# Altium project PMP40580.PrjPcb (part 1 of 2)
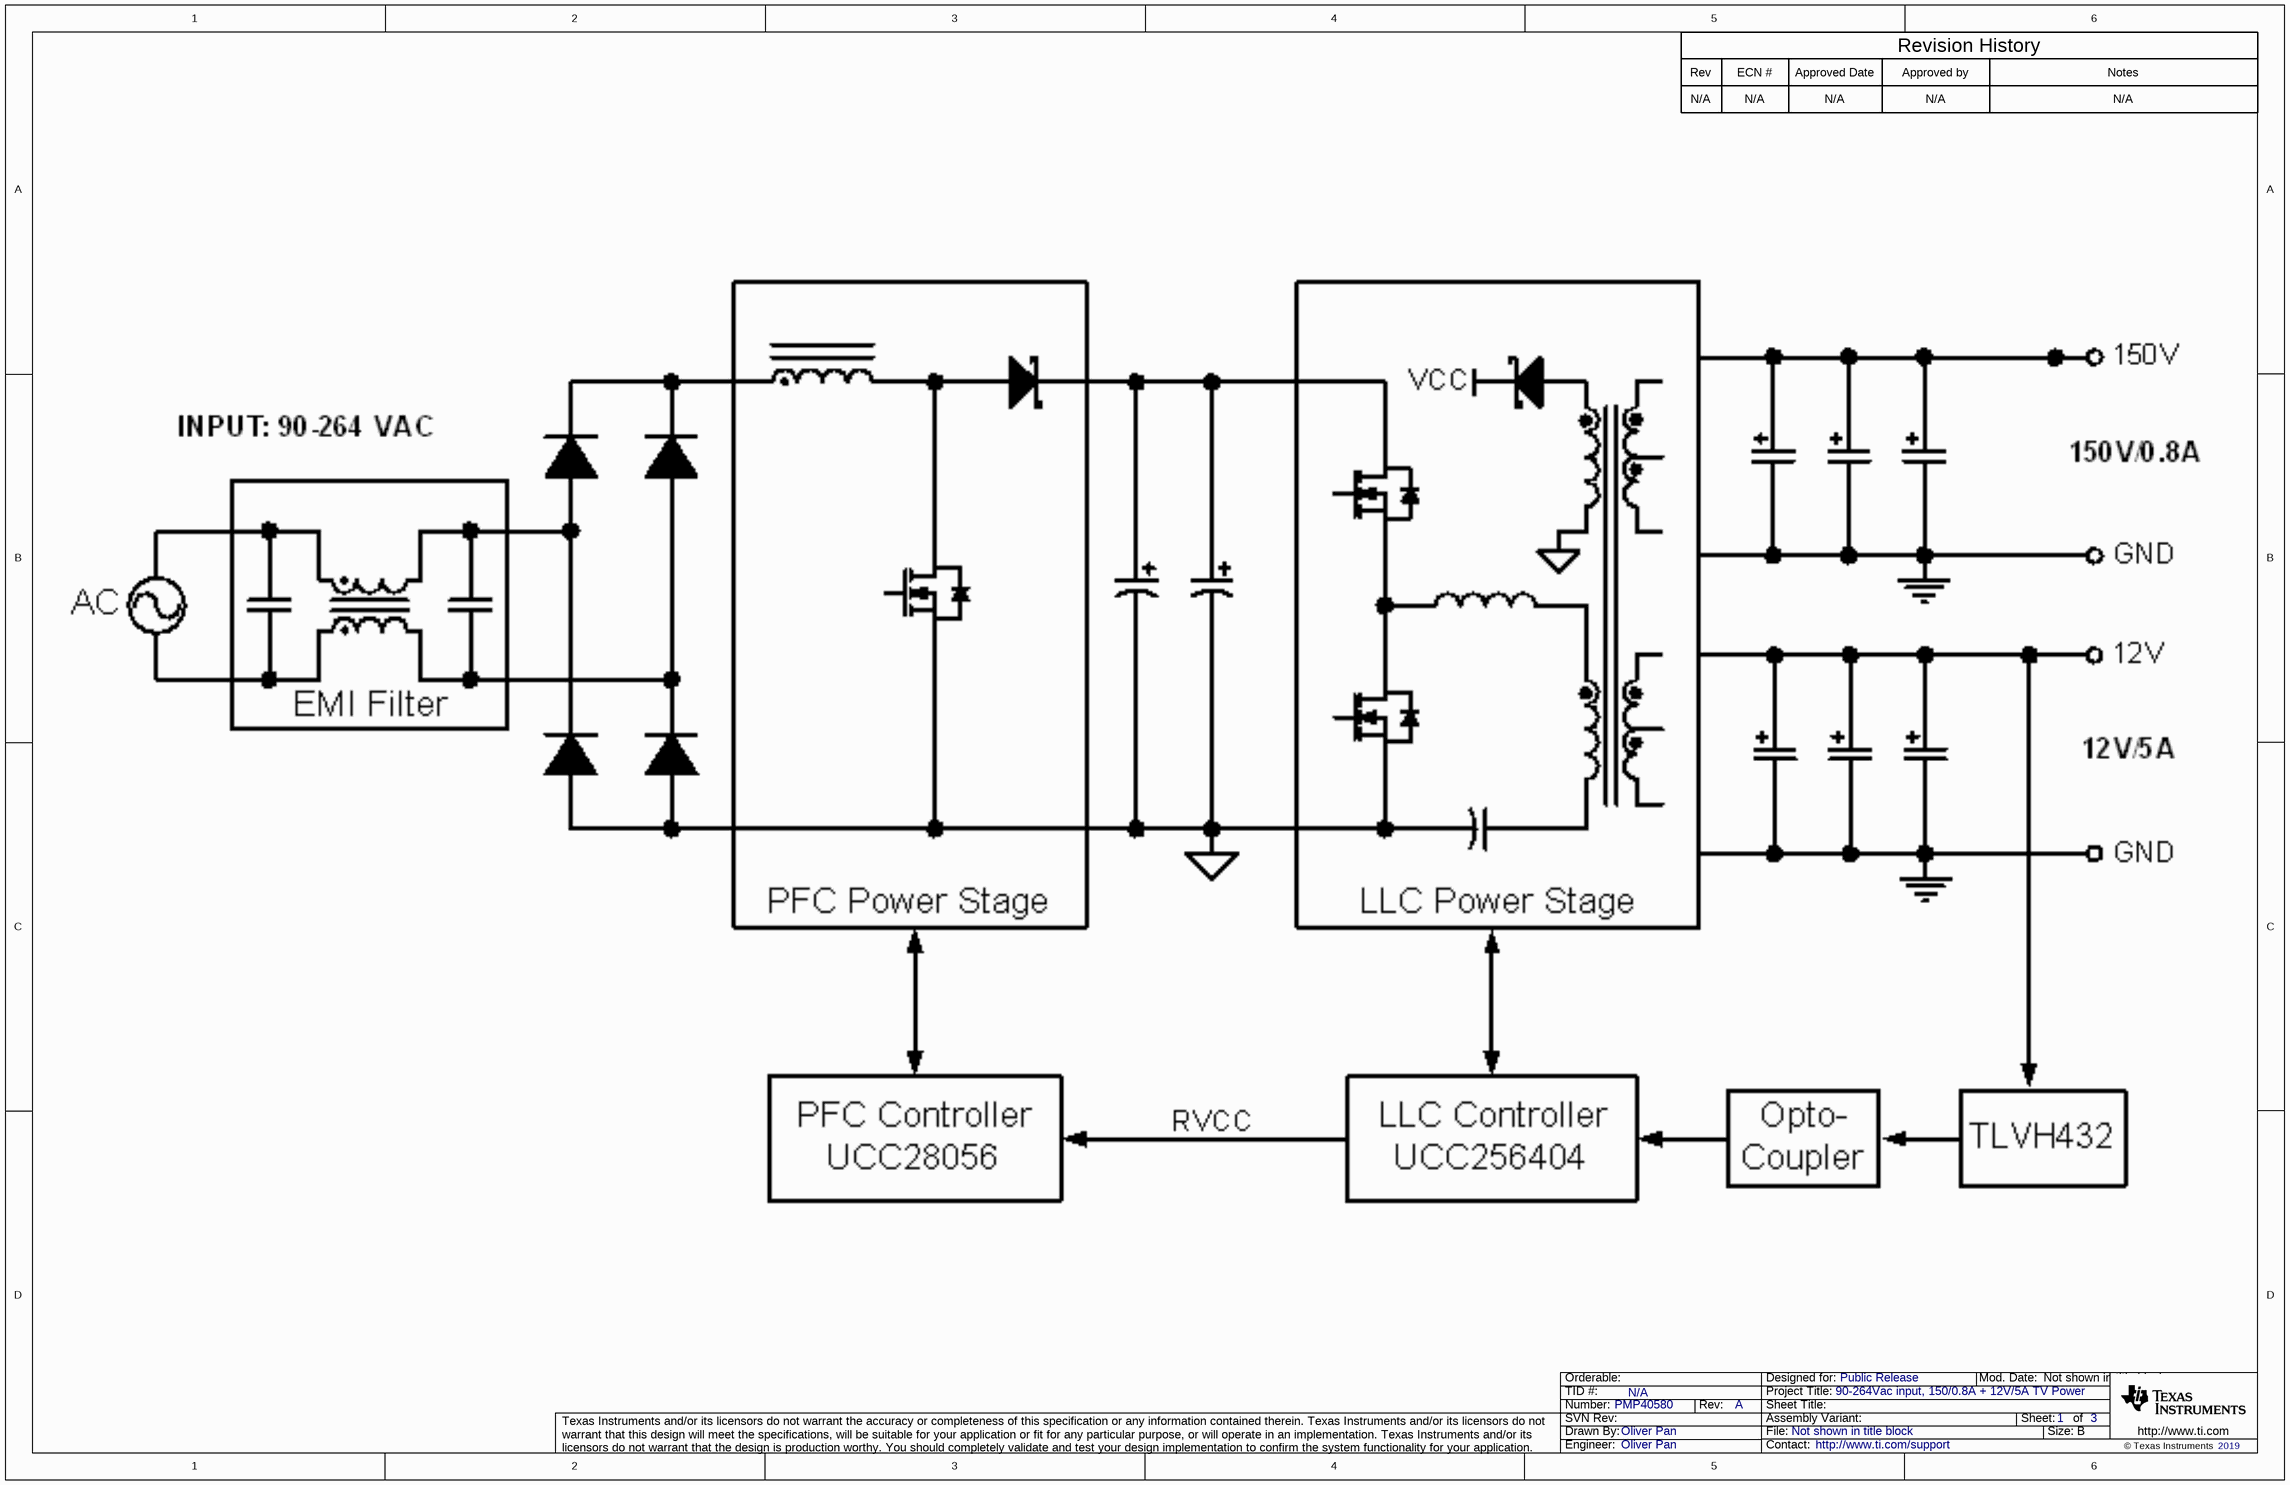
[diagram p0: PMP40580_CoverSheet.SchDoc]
CopyrightYear: 2019; PCB_Layout: Oliver Pan; PCB_Rev: A; PRJ_Customer: Public Release; PRJ_Engineer: Oliver Pan; PRJ_Number: PMP40580; PRJ_Title: 90-264Vac input, 150/0.8A + 12V/5A TV Power; SCH_Rev: A; TechSupport: http://www.ti.com/support; TID: N/A
3 sheets, 237 parts. Net scope: flat (ports and power ports of the same name join across sheets).
Board file: PMP40580_PCB.PcbDoc
Sheets:
  PMP40580_CoverSheet.SchDoc
  PMP40580_PFC.SchDoc
  PMP40580_LLC.SchDoc

## Sheet PMP40580_CoverSheet.SchDoc
size 431 x 279 mm; Date: Not shown in title block; ApprovedBy: Not shown in title block; CheckedBy: Not shown in title block; Author: Not shown in title block; CompanyName: Not shown in title block; DrawnBy: Oliver Pan; Engineer: Not shown in title block; Organization: Not shown in title block; Address1: Not shown in title block; Address2: Not shown in title block; Address3: Not shown in title block; Address4: Not shown in title block; DocumentNumber: 1; Revision: Use project parameter SCH_Rev; SheetNumber: 1; SheetTotal: 3; PageSetup: Record=PageOptions¦CenterHorizontal=True¦CenterVertical=True¦PrintScale=1.00¦XCorrection=1.00¦YCorrection=1.00¦PrintKind=0¦BorderSize=5000000¦LeftOffset=0¦BottomOffset=0¦Orientation=2¦PaperLength=1000¦PaperWidth=1000¦Scale=100¦PaperSource=15¦PrintQuality=600¦MediaType=1¦DitherType=10¦PaperKind=Letter¦PrintScaleMode=1

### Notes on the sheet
- Rev
- N/A
- ECN #
- Approved Date
- Approved by
- Revision History
- Notes

## Sheet PMP40580_PFC.SchDoc
size 431 x 279 mm; Date: Not shown in title block; ApprovedBy: Not shown in title block; CheckedBy: Not shown in title block; Author: Not shown in title block; CompanyName: Not shown in title block; DrawnBy: Oliver Pan; Engineer: Not shown in title block; Organization: Not shown in title block; Address1: Not shown in title block; Address2: Not shown in title block; Address3: Not shown in title block; Address4: Not shown in title block; DocumentNumber: 1; Revision: Use project parameter SCH_Rev; SheetNumber: 2; SheetTotal: 3; PageSetup: Record=PageOptions¦CenterHorizontal=True¦CenterVertical=True¦PrintScale=1.00¦XCorrection=1.00¦YCorrection=1.00¦PrintKind=0¦BorderSize=5000000¦LeftOffset=0¦BottomOffset=0¦Orientation=2¦PaperLength=1000¦PaperWidth=1000¦Scale=100¦PaperSource=15¦PrintQuality=600¦MediaType=1¦DitherType=10¦PaperKind=Letter¦PrintScaleMode=1
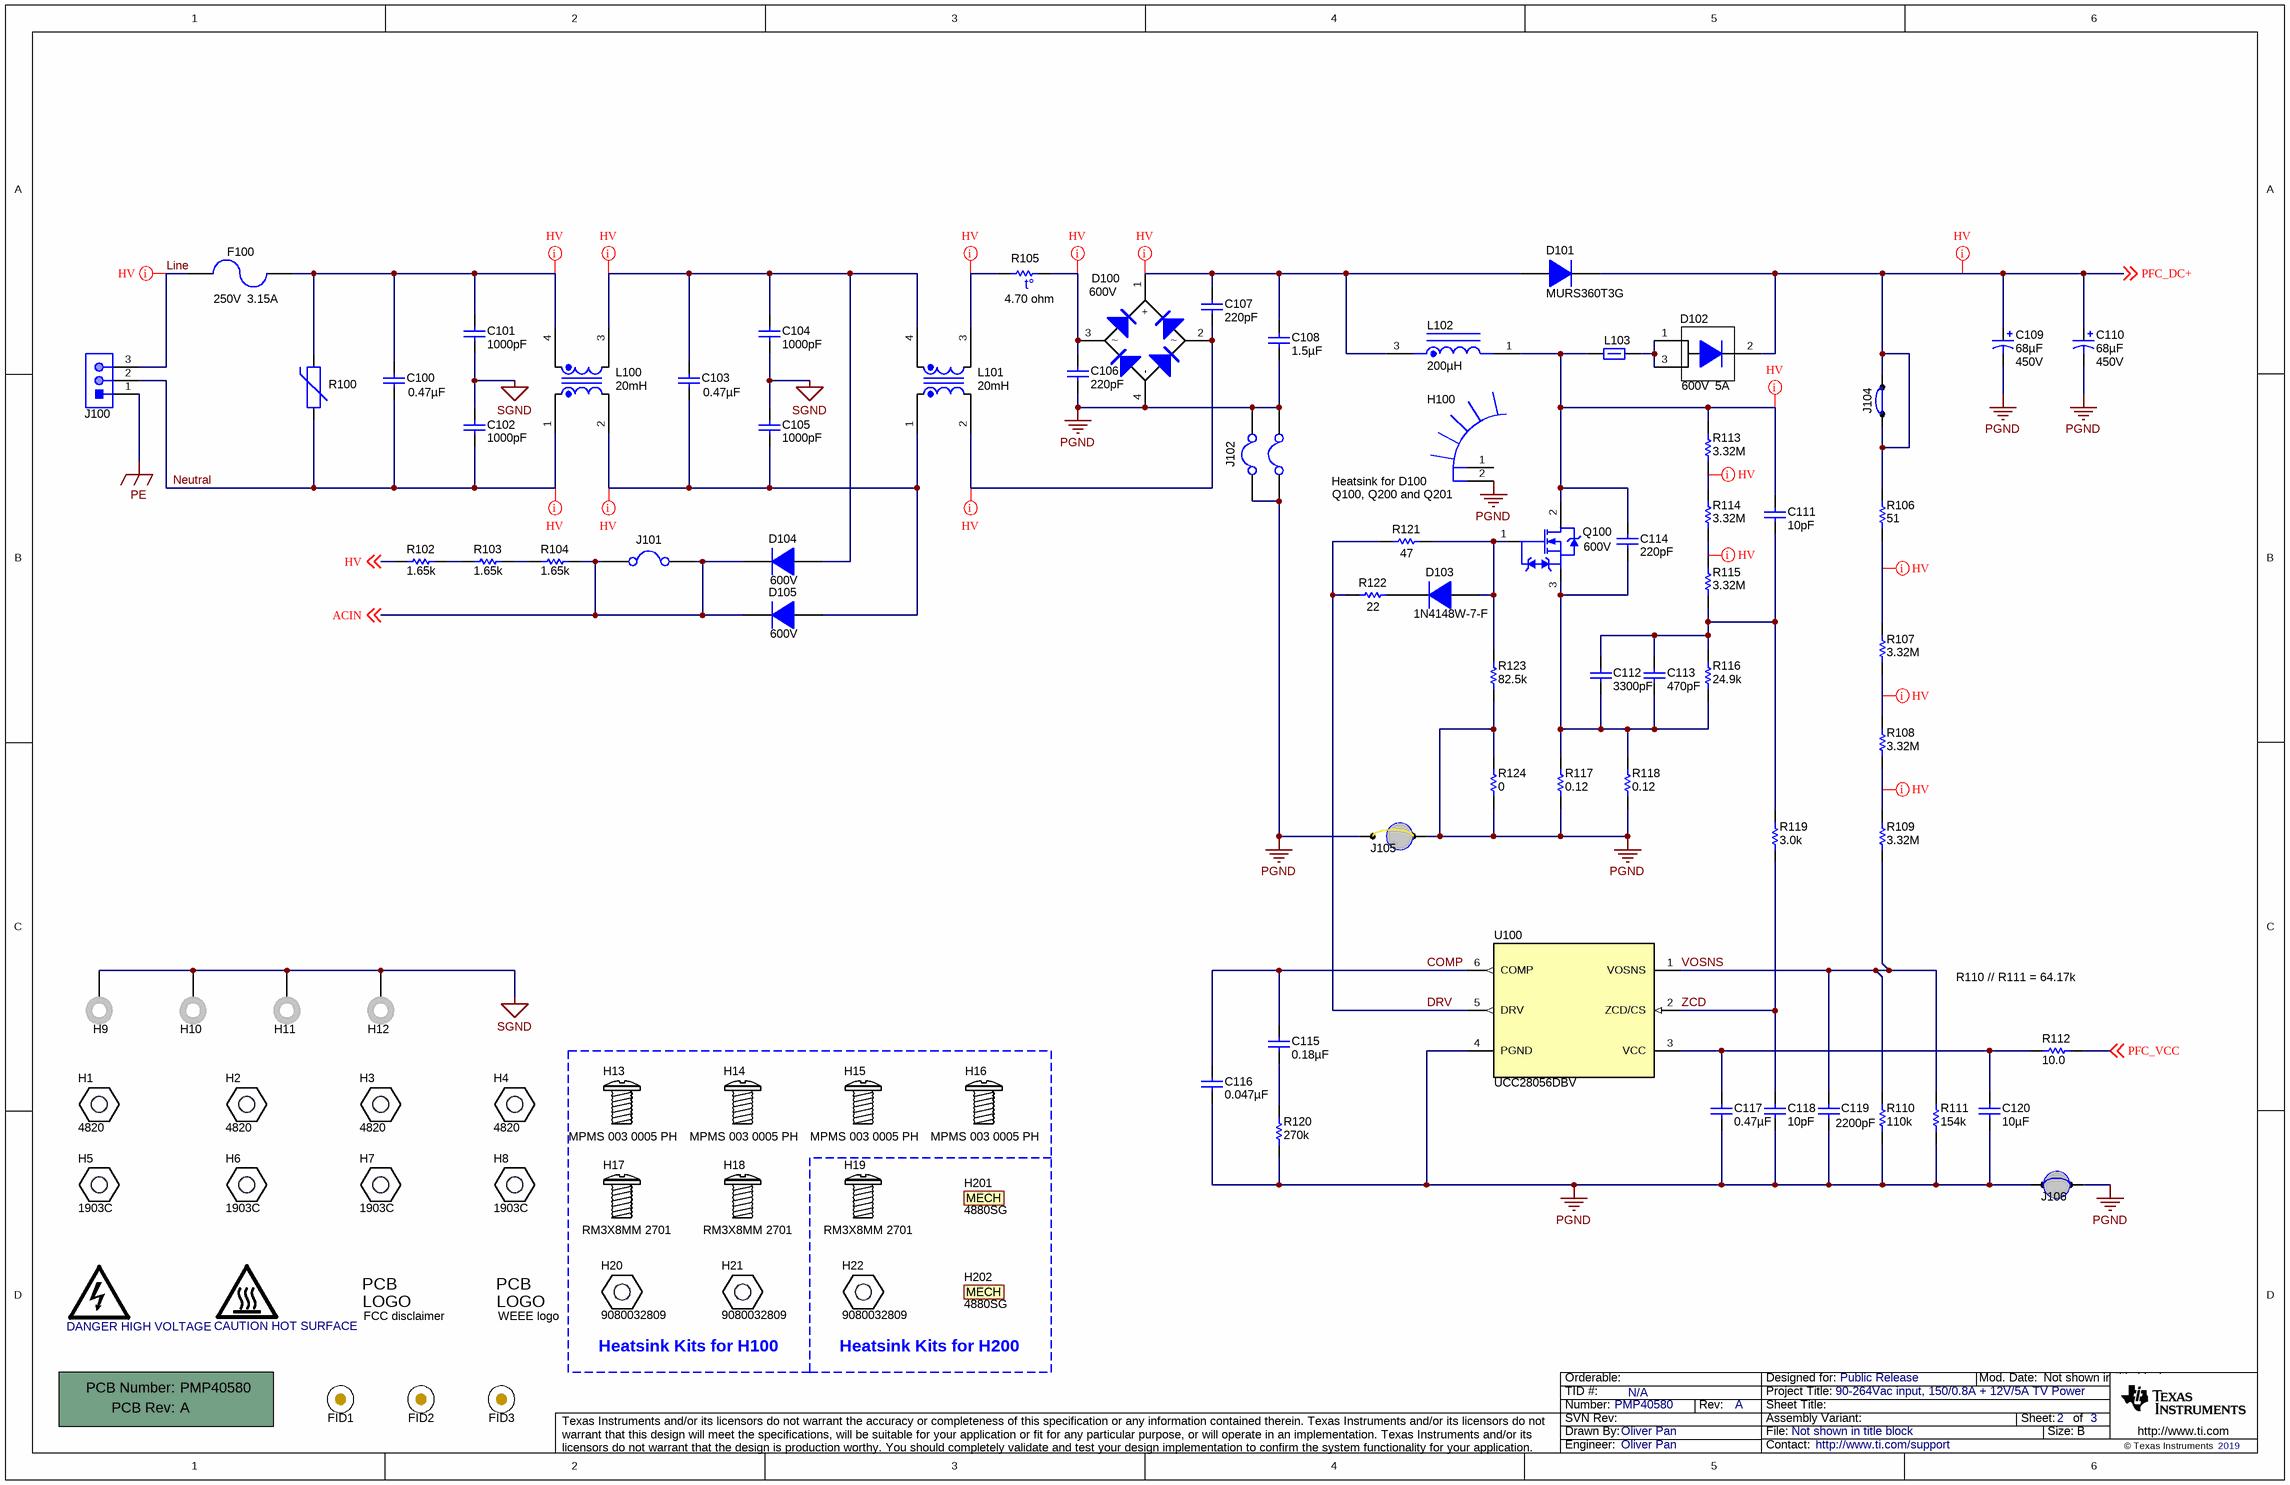
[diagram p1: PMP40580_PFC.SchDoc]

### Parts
!PCB  Printed Circuit Board  (value not drawn)  (mechanical)
C100  value 0.47µF  [CAPRR2250W80L2550T850H1750]  (hidden comment: ECQ-UAAF474M)
C101  ValueDisplayed: 1000pF  [CD45_700x600x1100]  (hidden comment: CD45-E2GA102M-NKA)
C102  ValueDisplayed: 1000pF  [CD45_700x600x1100]  (hidden comment: CD45-E2GA102M-NKA)
C103  value 0.47µF  [CAPRR2250W80L2550T850H1750]  (hidden comment: ECQ-UAAF474M)
C104  ValueDisplayed: 1000pF  [CD45_700x600x1100]  (hidden comment: CD45-E2GA102M-NKA)
C105  ValueDisplayed: 1000pF  [CD45_700x600x1100]  (hidden comment: CD45-E2GA102M-NKA)
C106  ValueDisplayed: 220pF  [CC45_850x500x1250]  (hidden comment: CC45SL3AD221JYNNA)
C107  ValueDisplayed: 220pF  [CC45_850x500x1250]  (hidden comment: CC45SL3AD221JYNNA)
C108  ValueDisplayed: 1.5µF  [ECQE_2570x820x1720]  (hidden comment: ECQ-E2W155KH)
C109  ValueDisplayed: 68µF  Value2: 450V  [BXW_1250x5000_Horizontal_DOWN]  (hidden comment: 450BXW68MEFC12.5X45)
C110  ValueDisplayed: 68µF  Value2: 450V  [BXW_1250x5000_Horizontal_DOWN]  (hidden comment: 450BXW68MEFC12.5X45)
C111  ValueDisplayed: 10pF  [1206]  (hidden comment: VJ1206A100JXGAT5Z)
C112  ValueDisplayed: 3300pF  [0805_HV]  (hidden comment: GRM2165C1H332JA01D)
C113  ValueDisplayed: 470pF  [0805_HV]  (hidden comment: 08055A471JAT2A)
C114  ValueDisplayed: 220pF  [CC45_850x500x1250]  (hidden comment: CC45SL3AD221JYNNA)
C115  ValueDisplayed: 0.18µF  [0805_HV]  (hidden comment: GRM21BR71E184KA01L)
C116  ValueDisplayed: 0.047µF  [0805_HV]  (hidden comment: GRM219R71E473KA01D)
C117  ValueDisplayed: 0.47µF  [0805_HV]  (hidden comment: GRM21BR71H474KA88L)
C118  ValueDisplayed: 10pF  [0805_HV]  (hidden comment: 08055A100JAT2A)
C119  ValueDisplayed: 2200pF  [0805_HV]  (hidden comment: GRM2165C1H222JA01D)
C120  ValueDisplayed: 10µF  [0805_HV]  (hidden comment: GRM21BZ71E106KE15L)
D100  value 600V  [FP-KBJ608G_BENT]  (hidden comment: TS15P05G)
D101  MURS360T3G  [SMC]
D102  value 600V  Value1: 5A  [DPAK]  (hidden comment: MURHD560T4G)
D103  1N4148W-7-F  [SOD-123]
D104  value 600V  [SMA]  (hidden comment: MURA160T3G)
D105  value 600V  [SMA]  (hidden comment: MURA160T3G)
F100  VAC_V: 250V  Irating_A: 3.15A  [FUSE_215]  (hidden comment: 02153.15MXEP)
FID1  Fiducial  [Fiducial10-20]  (value not drawn)
FID2  Fiducial  [Fiducial10-20]  (value not drawn)
FID3  Fiducial  [Fiducial10-20]  (value not drawn)
H1  4820  [KEYSTONE_4820]
H2  4820  [KEYSTONE_4820]
H3  4820  [KEYSTONE_4820]
H4  4820  [KEYSTONE_4820]
H5  1903C  [KEYSTONE_1903C]
H6  1903C  [KEYSTONE_1903C]
H7  1903C  [KEYSTONE_1903C]
H8  1903C  [KEYSTONE_1903C]
H9  (no value)  [GND CONNECT]
H10  (no value)  [GND CONNECT]
H11  (no value)  [GND CONNECT]
H12  (no value)  [GND CONNECT]
H13  MPMS 003 0005 PH  [BuildingFastener_MPMS_003_0005_PH]
H14  MPMS 003 0005 PH  [BuildingFastener_MPMS_003_0005_PH]
H15  MPMS 003 0005 PH  [BuildingFastener_MPMS_003_0005_PH]
H16  MPMS 003 0005 PH  [BuildingFastener_MPMS_003_0005_PH]
H17  RM3X8MM 2701  [APM_RM3X8MM 2701]
H18  RM3X8MM 2701  [APM_RM3X8MM 2701]
H19  RM3X8MM 2701  [APM_RM3X8MM 2701]
H20  9080032809  [9080032809]
H21  9080032809  [9080032809]
H22  9080032809  [9080032809]
H100  SK443100SA  [SK-443-AL-100]  (value not drawn)
H201  4880SG  (mechanical)
H202  4880SG  (mechanical)
J100  (no value)  [691312410003]
J101  923345-08-C  [FP-923345-08-C_JUMPER2-MFG]  (value not drawn)
J102  923345-08-C  [FP-923345-08-C_JUMPER2-MFG]  (value not drawn)
J103  923345-08-C  [FP-923345-08-C_JUMPER2-MFG]  (value not drawn)
J104  923345-06-C  [CONN_923345-06-C]  (value not drawn)
J105  923345-04-C  [3M_923345-04-C]  (value not drawn)
J106  923345-06-C  [CONN_923345-06-C]  (value not drawn)
L100  ValueDisplayed: 20mH  [JLB20213]  (hidden comment: JLB20213)
L101  ValueDisplayed: 20mH  [JLB20213]  (hidden comment: JLB20213)
L102  ValueDisplayed: 200µH  [JLC42178]  (hidden comment: JLC42184)
L103  28L0138-10R-10  [28L0138]  (value not drawn)
LOGO1  DANGER HIGH VOLTAGE  [IEC_HighVoltage_Medium]  (no BOM)
LOGO2  CAUTION HOT SURFACE  [IEC_HotSurface_Medium]  (no BOM)
Logo3  FCC disclaimer  [FCC_disclaimer]  (no BOM)
Logo4  WEEE logo  [WEEE_Minimum]  (no BOM)
Q100  value 600V  [TO-220FP_Horizontal_100mil_Standoff2300]  (hidden comment: STF24N60DM2)
R100  V300LA2P  [S237 - Horizontal_Down]  (value not drawn)
R102  ValueDisplayed: 1.65k  [1206L]  (hidden comment: CRCW12061K65FKEA)
R103  ValueDisplayed: 1.65k  [1206L]  (hidden comment: CRCW12061K65FKEA)
R104  ValueDisplayed: 1.65k  [1206L]  (hidden comment: CRCW12061K65FKEA)
R105  value 4.70 ohm  [S237 - Horizontal_Down]  (hidden comment: B57237S0479M000)
R106  ValueDisplayed: 51  [1206]  (hidden comment: CRCW120651R0JNEA)
R107  ValueDisplayed: 3.32M  [1206]  (hidden comment: CRCW12063M32FKEA)
R108  ValueDisplayed: 3.32M  [1206]  (hidden comment: CRCW12063M32FKEA)
R109  ValueDisplayed: 3.32M  [1206]  (hidden comment: CRCW12063M32FKEA)
R110  ValueDisplayed: 110k  [0805_HV]  (hidden comment: CRCW0805110KFKEA)
R111  ValueDisplayed: 154k  [0805_HV]  (hidden comment: CRCW0805154KFKEA)
R112  ValueDisplayed: 10.0  [1206]  (hidden comment: CRCW120610R0FKEA)
R113  ValueDisplayed: 3.32M  [1206]  (hidden comment: CRCW12063M32FKEA)
R114  ValueDisplayed: 3.32M  [1206]  (hidden comment: CRCW12063M32FKEA)
R115  ValueDisplayed: 3.32M  [1206]  (hidden comment: CRCW12063M32FKEA)
R116  ValueDisplayed: 24.9k  [0805_HV]  (hidden comment: ERJ-6ENF2492V)
R117  ValueDisplayed: 0.12  [1206]  (hidden comment: ERJ-8RSJR12V)
R118  ValueDisplayed: 0.12  [1206]  (hidden comment: ERJ-8RSJR12V)
R119  ValueDisplayed: 3.0k  [0805_HV]  (hidden comment: CRCW08053K00JNEA)
R120  ValueDisplayed: 270k  [0805_HV]  (hidden comment: CRCW0805270KJNEA)
R121  ValueDisplayed: 47  [0805_HV]  (hidden comment: CRCW080547R0JNEA)
R122  ValueDisplayed: 22  [0805_HV]  (hidden comment: CRCW080522R0JNEA)
R123  ValueDisplayed: 82.5k  [0805_HV]  (hidden comment: CRCW080582K5FKEA)
R124  ValueDisplayed: 0  [1206]  (hidden comment: CRCW12060000Z0EA)
U100  UCC28056DBV  [DBV0006A_N]

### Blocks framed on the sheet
Heatsink Kits for H100: H13-H18 H20 H21

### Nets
PE: J100.1
PGND: C106.1 C108.2 C109.2(-) C110.2(-) C116.2 C117.2 C118.2 C119.2 C120.2 D100.4(-) H100.2 J102.1 J102.2 J103.1 J103.2 J105.1 J105.2 J106.1 J106.2 R110.1 R111.1 R117.1 R118.1 R120.1 R123.1 R124.1 R124.2 U100.4(PGND)
SGND: C101.2 C102.2 C104.1 C105.2 H9.1 H10.1 H11.1 H12.1
ACIN: D104.1(K) D105.1(K) J101.1 J101.2 R104.2 ; off-sheet ACIN
COMP: C115.1 C116.1 U100.6(COMP)
DRV: R121.1 R122.1 U100.5(DRV)
HV: R102.1 ; off-sheet HV
Line: F100.2 J100.3
Neutral: C100.2 C102.1 J100.2 L100.1 R100.1
PFC_DC+: C109.1(+) C110.1(+) D101.1(K) D102.2(K) J104.1 J104.2 R106.2 ; off-sheet PFC_DC+
PFC_VCC: R112.2 ; off-sheet PFC_VCC
VOSNS: C119.1 R109.1 R110.2 R111.2 U100.1(VOSNS)
ZCD: C118.1 R119.1 U100.2(ZCD/CS)
NetC100_1: C100.1 C101.1 F100.1 L100.4 R100.2
NetC103_1: C103.1 C104.2 D104.2(A) L100.3 L101.4
NetC103_2: C103.2 C105.1 D105.2(A) L100.2 L101.1
NetC106_2: C106.2 D100.3 R105.2
NetC107_1: C107.1 D100.2 L101.2
NetC107_2: C107.2 C108.1 D100.1(+) D101.2(A) L102.3
NetC111_1: C111.1 C114.2 L102.1 L103.1 Q100.2(D) R113.2
NetC111_2: C111.2 C112.1 C113.1 R115.1 R116.2 R119.2
NetC112_2: C112.2 C113.2 C114.1 Q100.3(S) R116.1 R117.2 R118.2
NetC115_2: C115.2 R120.2
NetC117_1: C117.1 C120.1 R112.1 U100.3(VCC)
NetD102_1: D102.1(A) D102.3(A) L103.2
NetD103_1: D103.1(K) R122.2
NetD103_2: D103.2(A) Q100.1(G) R121.2 R123.2
NetL101_3: L101.3 R105.1
NetR102_2: R102.2 R103.1
NetR103_2: R103.2 R104.1
NetR106_1: R106.1 R107.2
NetR107_1: R107.1 R108.2
NetR108_1: R108.1 R109.2
NetR113_1: R113.1 R114.2
NetR114_1: R114.1 R115.2

Not connected (* = marked no-connect by the designer): H100 1

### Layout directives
rule Clearance Constraint [Clearance = 80mil]: Line, NetC100_1, NetC103_1, NetC103_2, NetC106_2, NetC107_1, NetC107_2, NetC111_1, NetL101_3, NetR106_1, NetR107_1, NetR108_1, NetR113_1, NetR114_1, Neutral, PFC_DC+

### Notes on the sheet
- Heatsink for D100
- (near H100) Q100, Q200 and Q201
- R110 // R111 = 64.17k
- Heatsink Kits for H200

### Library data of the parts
!PCB = CMP-0003618-2: Manufacturer: Any; PartNumber: PMP40580
C100 C103 = ECQ-U2A474ML: CAP, Film, 0.47 µF, 275 V,+/- 20%, TH; Manufacturer: Panasonic; Dielectric Material: PP; Voltage Rating (AC): 275V; Lead/Base Style: Straight; Lead Diameter: 0.8mm
C101 C102 C104 C105 = CD45-E2GA102M-NKA: CAP, CERM, 1000 pF, X1 440 VAC/Y1 400 VAC, +/- 20%, E, D7xT6mm; Manufacturer: TDK; Polarized: N; CompType: Capacitor; Value: 1000pF; U/M: EA; Cap_F: 0.000000001; Tolerance_%: 20; TaMin_C: -25; TaMax_C: 125; Cap_Case: 7x6x11mm; SizeArea_mm2: 63.9; SizeAreaWB_mm2: 101.2; SizeX_mm: 10.65; SizeY_mm: 6; SizeZ_mm: 11; AEC Category: Q200; AC_Safety: X1Y1; VAC_X: 440; VAC_Y: 400
C106 C107 C114 = CC45SL3AD221JYNNA: CAP, CERM, 220 pF, 1000 V,+/- 5%, SL, D8.5xT5mm; Manufacturer: TDK; Polarized: N; CompType: Capacitor; Value: 220pF; U/M: EA; Cap_F: 0.00000000022; Tolerance_%: 5; VDC_V: 1000; Value2: 1000V; TaMin_C: -25; TaMax_C: 125; Cap_Case: 8.5x5x12.5mm; SizeArea_mm2: 42.5; SizeAreaWB_mm2: 73.5; SizeX_mm: 8.5; SizeZ_mm: 12.5; AEC Category: Q200
C108 = ECQ-E2W155KH: CAP, Film, 1.5 µF, 450 V,+/- 10%, TH; Manufacturer: Panasonic; Polarized: N; CompType: Capacitor; Value: 1.5uF; U/M: EA; Cap_F: 0.0000015; Tolerance_%: 10; VDC_V: 450; Value2: 450V; TaMin_C: -40; TaMax_C: 105; AEC Category: Q200; Green_Lifecycle: Not Set; Green_REACh: Incomplete
C109 C110 = 450BXW68MEFC12.5X45: CAP, AL, 68 µF, 450 V, +/- 20%, TH; Manufacturer: Rubycon; Polarized: Y; CompType: Capacitor; Value: 68uF; U/M: EA; Cap_F: 0.000068; Tolerance_%: 20; Value1: Unknown; VDC_V: 450; IRMS_A: 0.61; TaMin_C: -40; TaMax_C: 105; Cap_Case: 12.5X45mm; SizeAreaWB_mm2: 210.25; SizeArea_mm2: 156.25; SizeX_mm: 12.5; SizeZ_mm: 47; AEC Category: Q200; AEC Qualified: N
C111 = VJ1206A100JXGAT5Z: CAP, CERM, 10 pF, 1000 V,+/- 5%, C0G/NP0, 1206; Manufacturer: Vishay-Vitramon; Polarized: N; CompType: Capacitor; Value: 10pF; U/M: EA; Cap_F: 0.00000000001; Tolerance_%: 5; VDC_V: 1000; Value2: 1000V; TaMin_C: -55; TaMax_C: 125; SizeArea_mm2: 5.12; SizeAreaWB_mm2: 10.92; SizeX_mm: 3.2; SizeY_mm: 1.6; SizeZ_mm: 1.35; AEC Category: Q200
C112 = GRM2165C1H332JA01D: CAP, CERM, 3300 pF, 50 V,+/- 5%, C0G/NP0, 0805; Manufacturer: MuRata; Polarized: N; CompType: Capacitor; Value: 3300pF; U/M: EA; Cap_F: 0.0000000033; Tolerance_%: 5; VDC_V: 50; Value2: 50V; TaMin_C: -55; TaMax_C: 125; Cap_Case: 0805; SizeArea_mm2: 2.5; SizeAreaWB_mm2: 6.75; SizeX_mm: 2; SizeY_mm: 1.25; SizeZ_mm: 1.45; AEC Category: Q200
C113 = 08055A471JAT2A: CAP, CERM, 470 pF, 50 V,+/- 5%, C0G/NP0, 0805; Manufacturer: AVX; Polarized: N; CompType: Capacitor; Value: 470pF; U/M: EA; Cap_F: 0.00000000047; Tolerance_%: 5; ESR_ohm: 0.159; Value1: 0.159 ohm; VDC_V: 50; Value2: 50V; TaMin_C: -55; TaMax_C: 125; Cap_Case: 0805; SizeArea_mm2: 2.5; SizeAreaWB_mm2: 6.75; SizeX_mm: 2; SizeY_mm: 1.25; SizeZ_mm: 1.45; AEC Category: Q200; Green_Lifecycle: Not Set; Green_REACh: Incomplete
C115 = GRM21BR71E184KA01L: CAP, CERM, 0.18 µF, 25 V,+/- 10%, X7R, 0805; Manufacturer: MuRata; Polarized: N; CompType: Capacitor; Value: 0.18uF; U/M: EA; Cap_F: 0.00000018; Tolerance_%: 10; VDC_V: 25; Value2: 25V; TaMin_C: -55; TaMax_C: 125; Cap_Case: 0805; SizeArea_mm2: 2.5; SizeAreaWB_mm2: 6.75; SizeX_mm: 2; SizeY_mm: 1.25; SizeZ_mm: 1.45; AEC Category: Q200
C116 = GRM219R71E473KA01D: CAP, CERM, 0.047 µF, 25 V,+/- 10%, X7R, 0805; Manufacturer: MuRata; Polarized: N; CompType: Capacitor; Value: 0.047uF; U/M: EA; Cap_F: 0.000000047; Tolerance_%: 10; VDC_V: 25; Value2: 25V; TaMin_C: -55; TaMax_C: 125; Cap_Case: 0805; SizeArea_mm2: 2.5; SizeAreaWB_mm2: 6.75; SizeX_mm: 2; SizeY_mm: 1.25; SizeZ_mm: 1.45; AEC Category: Q200
C117 = GRM21BR71H474KA88L: CAP, CERM, 0.47 µF, 50 V,+/- 10%, X7R, 0805; Manufacturer: MuRata; Polarized: N; CompType: Capacitor; Value: 0.47uF; U/M: EA; Cap_F: 0.00000047; Tolerance_%: 10; VDC_V: 50; Value2: 50V; TaMin_C: -55; TaMax_C: 125; Cap_Case: 0805; SizeArea_mm2: 2.5; SizeAreaWB_mm2: 6.75; SizeX_mm: 2; SizeY_mm: 1.25; SizeZ_mm: 1.45; AEC Category: Q200; Green_Lifecycle: Active; Green_REACh: Passed
C118 = 08055A100JAT2A: CAP, CERM, 10 pF, 50 V, +/- 5%, C0G/NP0, 0805; Manufacturer: AVX; Polarized: N; CompType: Capacitor; Value: 10pF; U/M: EA; Cap_F: 0.00000000001; Tolerance_%: 5; ESR_ohm: 1.561; Value1: 1.561 ohm; VDC_V: 50; Value2: 50V; TaMin_C: -55; TaMax_C: 125; Cap_Case: 0805; SizeArea_mm2: 2.5; SizeAreaWB_mm2: 6.75; SizeX_mm: 2; SizeY_mm: 1.25; SizeZ_mm: 1.45; AEC Category: Q200
C119 = GRM2165C1H222JA01D: CAP, CERM, 2200 pF, 50 V,+/- 5%, C0G/NP0, 0805; Manufacturer: MuRata; Polarized: N; CompType: Capacitor; Value: 2200pF; U/M: EA; Cap_F: 0.0000000022; Tolerance_%: 5; VDC_V: 50; Value2: 50V; TaMin_C: -55; TaMax_C: 125; Cap_Case: 0805; SizeArea_mm2: 2.5; SizeAreaWB_mm2: 6.75; SizeX_mm: 2; SizeY_mm: 1.25; SizeZ_mm: 1.45; AEC Category: Q200; Green_Lifecycle: Active; Green_REACh: Passed
C120 = GRM21BZ71E106KE15L: CAP, CERM, 10 µF, 25 V, +/- 10%, X7R, 0805; Manufacturer: MuRata; Polarized: N; CompType: Capacitor; Value: 10uF; U/M: EA; Cap_F: 0.00001; Tolerance_%: 10; Value1: Unknown; VDC_V: 25; Value2: 25V; TaMin_C: -55; TaMax_C: 125; Cap_Case: 0805; SizeArea_mm2: 2.5; SizeAreaWB_mm2: 6.75; SizeX_mm: 2; SizeY_mm: 1.25; SizeZ_mm: 1.45; AEC Category: Q200
D100 = GBU4J-BP: Diode, P-N-Bridge, 600 V, 15 A, TH; Manufacturer: Taiwan Semiconductor Corporation; U/M: EA; Vf_V: 1; Value1: 15A; Value2: 1V; Io_A: 4; Vr_V: 600; TJmax_C: 150; RJC_CperW: 2.2; SizeAreaWB_mm2: 130.5915; SizeArea_mm2: 75.6315; SizeX_mm: 22.05; SizeY_mm: 3.43; SizeZ_mm: 21.55; AEC Category: Q101
D101 = MURS360T3G: Diode, Ultrafast, 600 V, 3 A, SMC; Manufacturer: ON Semiconductor; U/M: EA; Vf_V: 1.25; Value: 600V; Value1: 3A; Value2: 1.25V; Io_A: 3; Vr_V: 600; TJmax_C: 175; RJC_CperW: 11; SizeAreaWB_mm2: 83.2686; SizeArea_mm2: 50.5686; SizeX_mm: 8.13; SizeY_mm: 6.22; SizeZ_mm: 2.6; AEC Category: Q101; Green_Lifecycle: Active; Green_REACh: Passed
D102 = CMP-0077041-3: Diode, Ultrafast, 600 V, 5 A, DPAK; Manufacturer: ON Semiconductor; SizeX_mm: 9.91; TJmax_C: 175°C; Green_Lifecycle: Not Set; Green_REACh: Incomplete; SizeZ_mm: 2.29; SizeY_mm: 6.54; SizeArea_mm2: 64.8114; SizeAreaWB_mm2: 101.7114; Value2: 2.7V; RJC_CperW: 2.5; AEC Category: Q101
D103 = 1N4148W-7-F: Diode, Ultrafast, 100 V, 0.15 A, SOD-123; Manufacturer: Diodes Inc.; U/M: EA; Vf_V: 1.25; Value: 100V; Value1: 0.15A; Value2: 1.25V; Io_A: 0.15; Vr_V: 100; TJmax_C: 150; SizeAreaWB_mm2: 13.095; SizeArea_mm2: 6.545; SizeX_mm: 3.85; SizeY_mm: 1.7; SizeZ_mm: 1.35; AEC Category: Q101
D104 D105 = MURA160T3G: Diode, Ultrafast, 600 V, 1 A, AEC-Q101, SMA; Manufacturer: ON Semiconductor; U/M: EA; Vf_V: 1.05; Value1: 1A; Value2: 1.05V; Io_A: 1; Vr_V: 600; TJmax_C: 175; SizeAreaWB_mm2: 37.3428; SizeArea_mm2: 16.3228; SizeX_mm: 5.59; SizeY_mm: 2.92; SizeZ_mm: 2.87; AEC Category: Q101; AEC Qualified: Y
F100 = 02153.15MXEP: Fuse, 3.15 A, 250 VAC, TH; Manufacturer: Littelfuse; Interrupt_AC: 1500; Rtyp_Ohm: 0.0283; MeltingTyp: 43.255
FID1-FID3 = CMP-0077181-1: Fiducial mark.  There is nothing to buy or mount.
H1-H4 = 4820: Standoff, Hex, 1"L #6-32 Nylon, M-F; Manufacturer: Keystone; SymbolCreator: a0412235; Green_Lifecycle: Active; Green_REACh: Passed
H5-H8 = CMP-0003679-1: Manufacturer: Keystone; CompType: Standoff
H9-H12 = 108-0740-001: GND connector
H13-H16 = MPMS 003 0005 PH: MACHINE SCREW PAN PHILLIPS M3 5mm; Manufacturer: B&F Fastener Supply; SymbolCreator: a0412235; Green_Lifecycle: Not Set; Green_REACh: Incomplete
H17-H19 = RM3X8MM 2701: MACHINE SCREW PAN PHILLIPS M3; Manufacturer: APM HEXSEAL; SymbolCreator: a0412235; Green_Lifecycle: Not Set; Green_REACh: Incomplete
H20-H22 = 9080032809: Hex Nuts: M3 X .5MM pitch DIN 934 A2 - 304 Stainless; Manufacturer: InStock Fasteners; SymbolCreator: a0412235; CompType: Nut; Green_Lifecycle: Not Set; Green_REACh: Incomplete
H100 = HeatSink_2840x500x600_PQFP64-PBH: Extruded Heatsink, 100mm, CUSTOM; Manufacturer: Texas Instruments; SymbolCreator: a0799628
H201 H202 = MechPart: TO-220 Mounting Kit; Manufacturer: Aavid Thermalloy; SymbolCreator: codlsc; CompType: Mechanical; U/M: EA
J100 = 691312410003: Serie 3124 - 7.62mm Open Horizontal PCB Header WR-TBL, 3 pin; Pin Number: 3; Gender: Male
J101-J103 = CMP-0086939-1: Manufacturer: 3M; ContactFinish: Tin
J104 J106 = 923345-06-C: Jumper Wire, 600mil spacing, Blue, pkg of 150, TH; Manufacturer: 3M; SymbolCreator: a0412235; Green_Lifecycle: Active; Green_REACh: Passed
J105 = 923345-04-C: Jumper Wire, 400 mil Spacing, Yellow, Pkg of 200; Manufacturer: 3M; SymbolCreator: Altium; Green_Lifecycle: Active; Green_REACh: Passed
L100 L101 = PMP40348 CM: Coupled inductor, 20 mH, 3 A, 0.16 ohm, TH; Manufacturer: Jewel; Value: 20mH; Ind_H: 20.0E-3; DCR_ohm: 0.16
L102 = BK-35: Inductor, 200 µH, 0.235 ohm, TH; Manufacturer: Jewel; SymbolCreator: Altium; Ind_H: 200.0E-6; DCR_ohm: 0.235; Value2: A; SizeAreaWB_mm2: 792.9856; SizeArea_mm2: 684.3456; SizeX_mm: 26.16; SizeZ_mm: 19.05; AEC Category: Q200; AEC Qualified: N
L103 = 28L0138-10R-10: Ferrite Bead, 75 ohm @ 100 MHz, 5 A, D3.51xL4.45mm; Manufacturer: Laird-Signal Integrity Products; ValueDisplayed: 75 ohm; Value: 75 ohm; Imax_A: 5; DCR_ohm: 0.01; Value1: 0.01 ohm; Value2: 5A; SizeAreaWB_mm2: 60.2243; SizeArea_mm2: 31.3443; SizeX_mm: 8.93; SizeY_mm: 3.51; SizeZ_mm: 3.76; ZTyp@100MHz_Ohm: 75; Green_Lifecycle: Not Set; Green_REACh: Incomplete
LOGO1 = CMP-0074835-1: IEC 61010-1 High Voltage Warning; Library Reference: IEC_HighVoltage; SymbolCreator: a0412235
LOGO2 = CMP-0074837-1: IEC 61010-1 Hot Surface Warning; Library Reference: IEC_HotSurface; SymbolCreator: a0412235
Logo3 = CMP-0074847-1: FCC_disclaimer; Library Reference: Logo
Logo4 = CMP-0074769-1
Q100 = STF24N60DM2: MOSFET, N-CH, 600 V, 18 A, TO-220FP; Manufacturer: STMicroelectronics; Alternate Manufacturer: None; U/M: EA; ChType: N; VdsMax_V: 600; Value1: ? ohm; Value2: 29 nC; QgTyp_nC: 29; Vgs_V: 25; IdsMax_A: 18; SizeAreaWB_mm2: 79.3; SizeArea_mm2: 45.9; SizeX_mm: 10.2; SizeY_mm: 4.5; SizeZ_mm: 20; AEC Category: Q101; Green_Lifecycle: Active; Green_REACh: Passed; SymbolCreator: x0208325
R100 = V300LA2P: VARISTOR 490V 1.2KA DISC 7MM; Manufacturer: Littelfuse; SymbolCreator: a0412235
R102-R104 = CMP-0016708-3: RES, 1.65 k, 1%, 0.25 W, AEC-Q200 Grade 0, 1206; Manufacturer: Vishay-Dale; Power_W: 250mW; TempCo: 100 ppm/C; Value_Code: 1k65; Value: 1.65k; EIA_Code: E96; SizeX_mm: 3.2; SizeY_mm: 1.6; SizeZ_mm: 1.35; Value2: 0.25W; SizeArea_mm2: 5.12; CompType: Resistor; AEC Qualified: Y; VDC_V: 200V; AEC Category: Q200; AEC Grade: 0
R105 = B57237S0479M000: Thermistor NTC, 4.70 ohm, 20%, 15x7mm; Manufacturer: TDK; Tolerance_%: 20; Power_W: 3.1; TaMin_C: -55; TaMax_C: 170; U/M: EA
R106 = CRCW120651R0JNEA: RES, 51, 5%, 0.25 W, 1206; Manufacturer: Vishay-Dale; CompType: Resistor; Value: 51; Value_Code: 51R0; Tolerance_%: 5; Power_W: 0.25; Value2: 0.25W; VDC_V: 200; TempCo: 200 ppm/C; SizeArea_mm2: 5.12; SizeX_mm: 3.2; SizeY_mm: 1.6; SizeZ_mm: 1.35; EIA_Code: E24; U/M: EA; AEC Category: Q200
R107-R109 R113-R115 = CRCW12063M32FKEA: RES, 3.32 M, 1%, 0.25 W, 1206; Manufacturer: Vishay-Dale; CompType: Resistor; Value: 3.32Meg; Res_ohm: 3320000; Value_Code: 3M32; Tolerance_%: 1; Power_W: 0.25; Value2: 0.25W; VDC_V: 200; TempCo: 100 ppm/C; SizeArea_mm2: 5.12; SizeX_mm: 3.2; SizeY_mm: 1.6; SizeZ_mm: 1.35; EIA_Code: E96; U/M: EA; AEC Category: Q200
R110 = CRCW0805110KFKEA: RES, 110 k, 1%, 0.125 W, 0805; Manufacturer: Vishay-Dale; CompType: Resistor; Value: 110k; Res_ohm: 110000; Tolerance_%: 1; Power_W: 0.125; Value2: 0.125W; VDC_V: 150; TempCo: 100 ppm/C; SizeArea_mm2: 2.5; SizeX_mm: 2; SizeY_mm: 1.25; SizeZ_mm: 1.45; EIA_Code: E96; U/M: EA; AEC Category: Q200; Green_Lifecycle: Active; Green_REACh: Passed
R111 = CRCW0805154KFKEA: RES, 154 k, 1%, 0.125 W, 0805; Manufacturer: Vishay-Dale; CompType: Resistor; Value: 154k; Res_ohm: 154000; Tolerance_%: 1; Power_W: 0.125; Value2: 0.125W; VDC_V: 150; TempCo: 100 ppm/C; SizeArea_mm2: 2.5; SizeX_mm: 2; SizeY_mm: 1.25; SizeZ_mm: 1.45; EIA_Code: E96; U/M: EA; AEC Category: Q200; Green_Lifecycle: Active; Green_REACh: Passed
R112 = CRCW120610R0FKEA: RES, 10.0, 1%, 0.25 W, 1206; Manufacturer: Vishay-Dale; CompType: Resistor; Value: 10.0; Res_ohm: 10; Value_Code: 10R0; Tolerance_%: 1; Power_W: 0.25; Value2: 0.25W; VDC_V: 200; TempCo: 100 ppm/C; SizeArea_mm2: 5.12; SizeX_mm: 3.2; SizeY_mm: 1.6; SizeZ_mm: 1.35; EIA_Code: E96; U/M: EA; AEC Category: Q200
R116 = ERJ-6ENF2492V: RES, 24.9 k, 1%, 0.125 W, 0805; Manufacturer: Panasonic; CompType: Resistor; Value: 24.9k; Res_ohm: 24900; Value_Code: 24k9; Tolerance_%: 1; Power_W: 0.125; Value2: 0.125W; TempCo: 100 ppm/C; SizeArea_mm2: 2.5; SizeX_mm: 2; SizeY_mm: 1.25; SizeZ_mm: 1.45; EIA_Code: E96; U/M: EA; AEC Category: Q200
R117 R118 = ERJ-8RSJR12V: RES, 0.12, 5%, 0.25 W, 1206; Manufacturer: Panasonic; CompType: Resistor; Value: 0.12; Value_Code: R120; Tolerance_%: 5; Power_W: 0.25; Value2: 0.25W; TempCo: 250 ppm/C; SizeArea_mm2: 5.12; SizeX_mm: 3.2; SizeY_mm: 1.6; SizeZ_mm: 1.35; EIA_Code: E24; U/M: EA; AEC Category: Q200
R119 = CRCW08053K00JNEA: RES, 3.0 k, 5%, 0.125 W, 0805; Manufacturer: Vishay-Dale; CompType: Resistor; Value: 3.0k; Res_ohm: 3000; Value_Code: 3k00; Tolerance_%: 5; Power_W: 0.125; Value2: 0.125W; VDC_V: 150; TempCo: 200 ppm/C; SizeArea_mm2: 2.5; SizeX_mm: 2; SizeY_mm: 1.25; SizeZ_mm: 1.45; EIA_Code: E24; U/M: EA; AEC Category: Q200
R120 = CRCW0805270KJNEA: RES, 270 k, 5%, 0.125 W, 0805; Manufacturer: Vishay-Dale; CompType: Resistor; Value: 270k; Res_ohm: 270000; Tolerance_%: 5; Power_W: 0.125; Value2: 0.125W; VDC_V: 150; TempCo: 200 ppm/C; SizeArea_mm2: 2.5; SizeX_mm: 2; SizeY_mm: 1.25; SizeZ_mm: 1.45; EIA_Code: E24; U/M: EA; AEC Category: Q200
R121 = CRCW080547R0JNEA: RES, 47, 5%, 0.125 W, 0805; Manufacturer: Vishay-Dale; CompType: Resistor; Value: 47; Value_Code: 47R0; Tolerance_%: 5; Power_W: 0.125; Value2: 0.125W; VDC_V: 150; TempCo: 200 ppm/C; SizeArea_mm2: 2.5; SizeX_mm: 2; SizeY_mm: 1.25; SizeZ_mm: 1.45; EIA_Code: E24; U/M: EA; AEC Category: Q200
R122 = CRCW080522R0JNEA: RES, 22, 5%, 0.125 W, 0805; Manufacturer: Vishay-Dale; CompType: Resistor; Value: 22; Value_Code: 22R0; Tolerance_%: 5; Power_W: 0.125; Value2: 0.125W; VDC_V: 150; TempCo: 200 ppm/C; SizeArea_mm2: 2.5; SizeX_mm: 2; SizeY_mm: 1.25; SizeZ_mm: 1.45; EIA_Code: E24; U/M: EA; AEC Category: Q200; Green_Lifecycle: Active; Green_REACh: Passed
R123 = CRCW080582K5FKEA: RES, 82.5 k, 1%, 0.125 W, 0805; Manufacturer: Vishay-Dale; CompType: Resistor; Value: 82.5k; Res_ohm: 82500; Value_Code: 82k5; Tolerance_%: 1; Power_W: 0.125; Value2: 0.125W; VDC_V: 150; TempCo: 100 ppm/C; SizeArea_mm2: 2.5; SizeX_mm: 2; SizeY_mm: 1.25; SizeZ_mm: 1.45; EIA_Code: E96; U/M: EA; AEC Category: Q200; Green_Lifecycle: Active; Green_REACh: Passed
R124 = CRCW12060000Z0EA: RES, 0, 5%, 0.25 W, 1206; Manufacturer: Vishay-Dale; CompType: Resistor; Value: 0; Value_Code: 0000; Tolerance_%: 5; Power_W: 0.25; Value2: 0.25W; VDC_V: 200; TempCo: 200 ppm/C; SizeArea_mm2: 5.12; SizeX_mm: 3.2; SizeY_mm: 1.6; SizeZ_mm: 1.35; EIA_Code: E24; U/M: EA; AEC Category: Q200; Green_Lifecycle: Active; Green_REACh: Passed
U100 = UCC28056DBV: 6-Pin Single-Phase Transition-Mode PFC Controller, DBV0006A (SOT-23-6); Manufacturer: Texas Instruments; SymbolCreator: Altium; SizeArea_mm2: 8.12; SizeAreaWB_mm2: 14.82; SizeX_mm: 2.8; SizeY_mm: 2.9; SizeZ_mm: 1.45; CompType: IC; U/M: EA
